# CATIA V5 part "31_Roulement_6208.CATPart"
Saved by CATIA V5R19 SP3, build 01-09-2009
Part number: 31_Roulement_6208
Bounding box of the stored display mesh (mm): x 0 to 18, y -40 to 40, z -40 to 40
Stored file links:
  C:\Users\Frédéric\Documents\WF\STSCPI 09-11\Projets\Projet multiplicateur eolienne\Maquette eolienne\Standard\31_Roulement_6208.CATPart
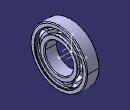
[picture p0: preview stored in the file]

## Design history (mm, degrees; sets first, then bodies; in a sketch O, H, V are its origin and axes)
AxisSystem1: origin (0, 0, 0), X (1, 0, 0), Y (0, 1, 0), Z (0, 0, 1)
Body1 "1" (main body)
  Solid1: solid without history
Body2 "2"
  Solid2: solid without history
Body3 "3"
  Solid3: solid without history
Body4 "4"
  Solid4: solid without history
Body5 "5"
  Solid5: solid without history
Body6 "6"
  Solid6: solid without history
Body7 "7"
  Solid7: solid without history
Body8 "8"
  Solid8: solid without history
Body9 "9"
  Solid9: solid without history
Body10 "10"
  Solid10: solid without history
Body11 "11"
  Solid11: solid without history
